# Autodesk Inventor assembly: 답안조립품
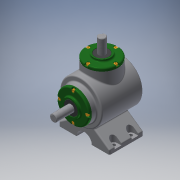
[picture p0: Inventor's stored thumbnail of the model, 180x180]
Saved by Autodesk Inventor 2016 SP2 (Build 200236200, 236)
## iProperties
Created: 2017-04
Part Number: 답안조립품
Material: 일반
Document SubType Name: Assembly
Designer: CAMTIC
Author: CAMTIC
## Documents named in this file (14)
- C:\Users\CAMTIC\Desktop\470407V1030\답안조립품.iam
- C:\Users\CAMTIC\Desktop\470407V1030\1-본체.ipt
- C:\Users\CAMTIC\Desktop\470407V1030\메인 베벨기어.ipt
- C:\Users\CAMTIC\Desktop\470407V1030\메인 축.ipt
- 메인 축.ipt
- C:\Users\CAMTIC\Desktop\470407V1030\베어링 6203.ipt
- C:\Users\CAMTIC\Desktop\470407V1030\볼트 M4.ipt
- C:\Users\CAMTIC\Desktop\470407V1030\서브 베벨기어.ipt
- C:\Users\CAMTIC\Desktop\470407V1030\서브 축.ipt
- 서브 축.ipt
- C:\Users\CAMTIC\Desktop\470407V1030\오일실 17 32 8.ipt
- C:\Users\CAMTIC\Desktop\470407V1030\커버.ipt
- C:\Users\CAMTIC\Desktop\470407V1030\키 4x4.ipt
- C:\Users\CAMTIC\Desktop\470407V1030\키 5x5.ipt
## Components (1 placed, 1 different names)
1. 1-본체:1
